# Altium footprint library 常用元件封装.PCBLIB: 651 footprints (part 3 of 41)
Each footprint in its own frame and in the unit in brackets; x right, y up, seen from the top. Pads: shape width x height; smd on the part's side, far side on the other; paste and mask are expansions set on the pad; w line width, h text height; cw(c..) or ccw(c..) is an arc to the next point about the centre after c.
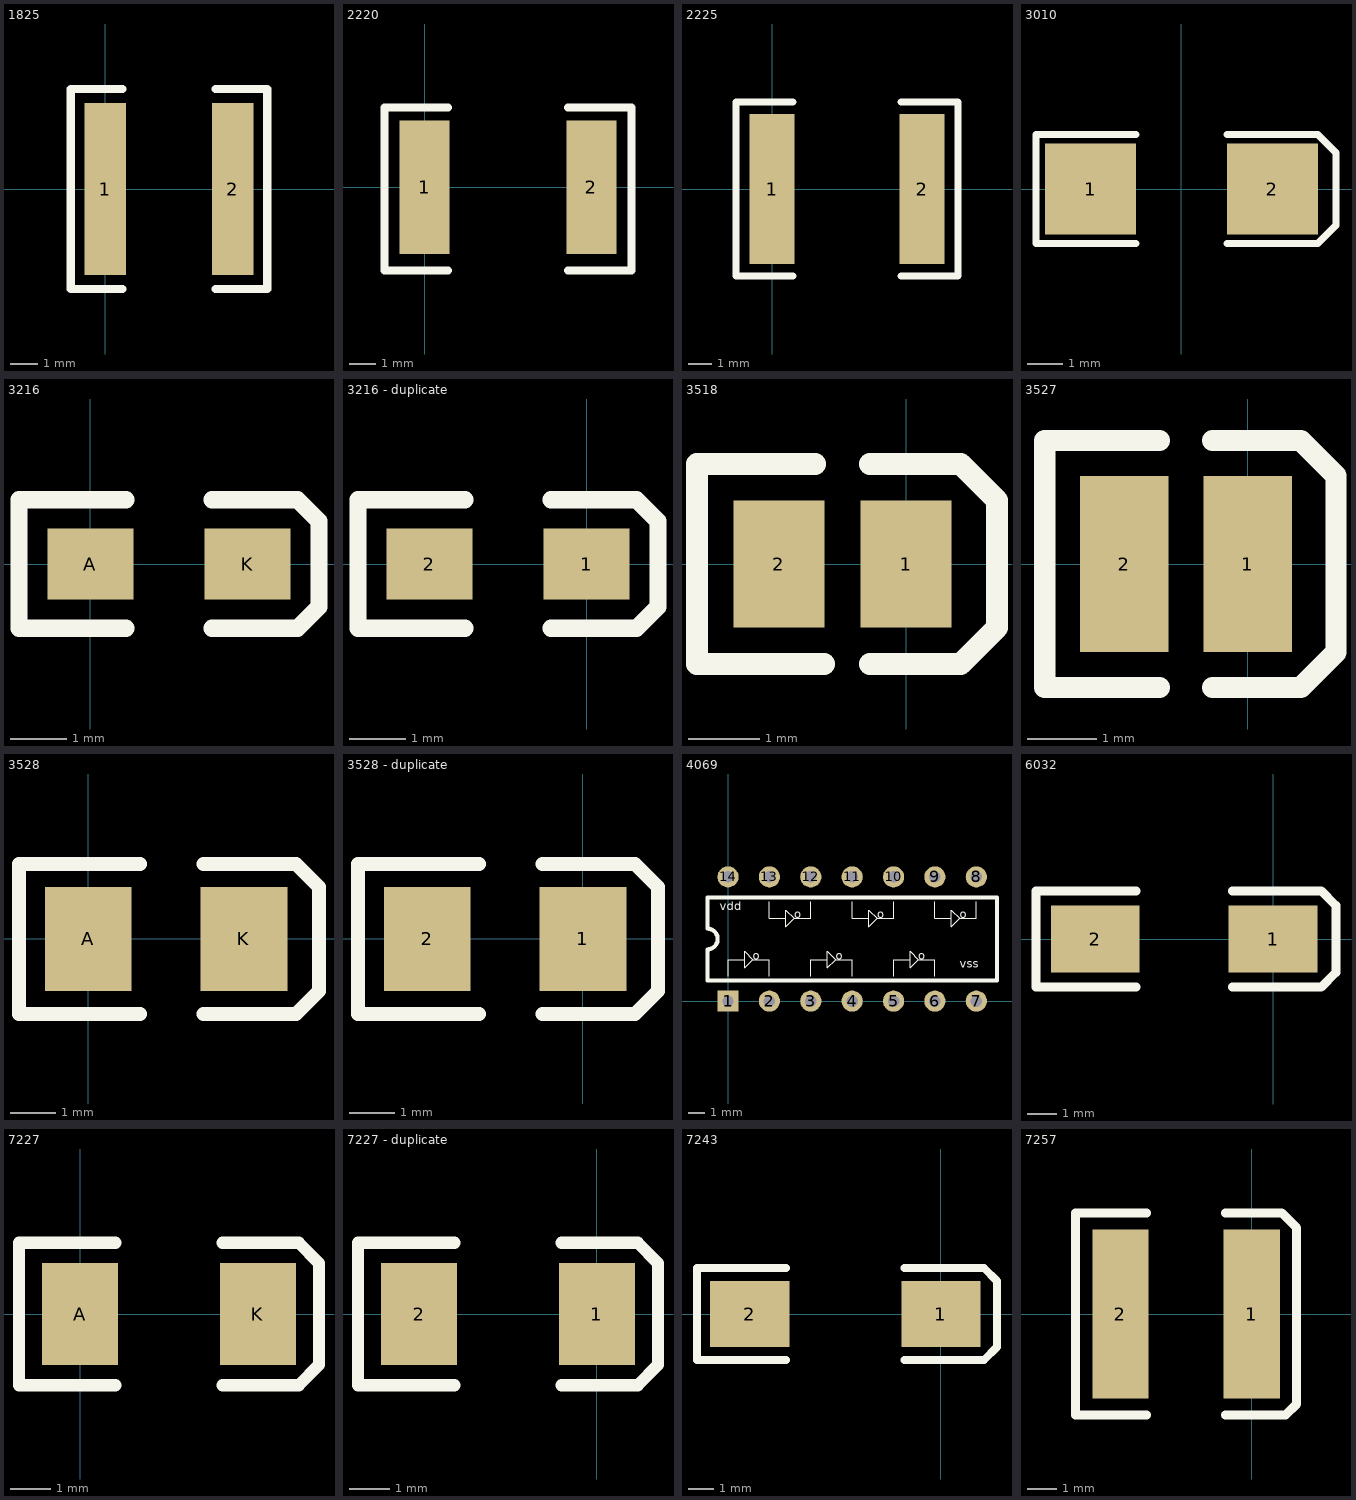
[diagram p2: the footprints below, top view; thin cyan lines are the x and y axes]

## 1825 [mil]
pads (2):
  rect 60x250 smd: 1(0,0) 2(185,0)
TopOverlay:
  lines w12: 25,-145 -50,-145 -50,145 25,145 ; 160,-145 235,-145 235,145 160,145

## 2220 [mil]
pads (2):
  rect 75x200 smd: 1(0,0) 2(250,0)
TopOverlay:
  lines w12: 35,-125 -60,-125 -60,120 35,120 ; 215,-125 310,-125 310,120 215,120

## 2225 [mil]
pads (2):
  rect 75x250 smd: 1(0,0) 2(250,0)
TopOverlay:
  lines w12: 35,-145 -60,-145 -60,145 35,145 ; 215,-145 310,-145 310,145 215,145

## 3010 [mil]
pads (2):
  rect 100x100 smd: 1(-100,0) 2(100,0)
TopOverlay:
  lines w8: -50,-60 -160,-60 -160,-50 -160,60 -50,60 ; 50,60 150,60 170,40 170,-40 150,-60 50,-60 80,-60

## 3216 [mil]
pads (2):
  rect 60x50 smd: A(0,0) K(110,0)
TopOverlay:
  lines w12: 25,-45 -50,-45 -50,45 25,45 ; 85,-45 145,-45 160,-30 160,30 145,45 85,45

## 3216 - duplicate [mil]
pads (2):
  rect 60x50 smd: 1(0,0) 2(-110,0)
TopOverlay:
  lines w12: -85,-45 -160,-45 -160,45 -85,45 ; -25,-45 35,-45 50,-30 50,30 35,45 -25,45

## 3518 [mil]
pads (2):
  rect 50x70 smd: 1(0,0) 2(-70,0)
TopOverlay:
  lines w12: -50,55 -115,55 -115,-55 -45,-55 ; -20,-55 30,-55 50,-35 50,35 30,55 -20,55

## 3527 [mil]
pads (2):
  rect 50x100 smd: 1(0,0) 2(-70,0)
TopOverlay:
  lines w12: -50,-70 -115,-70 -115,70 -50,70 ; -20,-70 30,-70 50,-50 50,50 30,70 -20,70

## 3528 [mil]
pads (2):
  rect 75x90 smd: A(0,0) K(135,0)
TopOverlay:
  lines w12: 45,-65 -60,-65 -60,65 45,65 ; 100,-65 180,-65 200,-45 200,45 180,65 100,65

## 3528 - duplicate [mil]
pads (2):
  rect 75x90 smd: 1(0,0) 2(-135,0)
TopOverlay:
  lines w12: -90,-65 -195,-65 -195,65 -90,65 ; -35,-65 45,-65 65,-45 65,45 45,65 -35,65

## 4069 [mm]
pads (14):
  rect 1.3x1.3 hole 0.7: 1(0,0)
  round 1.3 hole 0.7: 2(2.54,0) 3(5.08,0) 4(7.62,0) 5(10.16,0) 6(12.7,0) 7(15.24,0) 8(15.24,7.62) 9(12.7,7.62) 10(10.16,7.62) 11(7.62,7.62) 12(5.08,7.62) 13(2.54,7.62) 14(0,7.62)
TopOverlay:
  lines w0.051: 0,1.524 0,2.54 0.508,2.54 1.016,2.54 ; 2.54,1.524 2.54,2.54 1.524,2.54 ; 2.54,6.096 2.54,5.08 3.048,5.08 3.556,5.08 ; 5.08,1.524 5.08,2.54 5.588,2.54 6.096,2.54 ; 5.08,6.096 5.08,5.08 4.064,5.08 ; 7.62,1.524 7.62,2.54 6.604,2.54 ; 7.62,6.096 7.62,5.08 8.128,5.08 8.636,5.08 ; 10.16,1.524 10.16,2.54 10.668,2.54 11.176,2.54 ; 10.16,6.096 10.16,5.08 9.144,5.08 ; 12.7,1.524 12.7,2.54 11.684,2.54 ; 12.7,6.096 12.7,5.08 13.208,5.08 13.716,5.08 ; 15.24,6.096 15.24,5.08 14.224,5.08 ; 1.524,2.54 1.016,2.032 1.016,3.048 1.524,2.54 ; 4.064,5.08 3.556,4.572 3.556,5.588 4.064,5.08 ; 6.604,2.54 6.096,2.032 6.096,3.048 6.604,2.54 ; 9.144,5.08 8.636,4.572 8.636,5.588 9.144,5.08 ; 11.684,2.54 11.176,2.032 11.176,3.048 11.684,2.54 ; 14.224,5.08 13.716,4.572 13.716,5.588 14.224,5.08
  lines w0.254: -1.27,1.27 16.51,1.27 16.51,6.35 -1.27,6.35 -1.27,4.445 cw(c-1.27,3.81) -1.27,3.175 -1.27,1.27
  text "vss" at 14.224,2.032 h0.51
  text "vdd" at -0.508,5.588 h0.51
  text "o" at 4.064,5.08 h0.51
  text "o" at 9.144,5.08 h0.51
  text "o" at 14.224,5.08 h0.51
  text "o" at 11.684,2.54 h0.51
  text "o" at 6.604,2.54 h0.51
  text "o" at 1.524,2.54 h0.51

## 6032 [mil]
pads (2):
  rect 120x90 smd: 1(0,0) 2(-240,0)
TopOverlay:
  lines w12: -185,-65 -320,-65 -320,65 -185,65 ; -55,-65 65,-65 85,-45 85,45 65,65 -55,65

## 7227 [mil]
pads (2):
  rect 75x100 smd: A(0,0) K(175,0)
TopOverlay:
  lines w12: 35,-70 -60,-70 -60,70 35,70 ; 140,-70 215,-70 235,-50 235,50 215,70 140,70

## 7227 - duplicate [mil]
pads (2):
  rect 75x100 smd: 1(0,0) 2(-175,0)
TopOverlay:
  lines w12: -140,-70 -235,-70 -235,70 -140,70 ; -35,-70 40,-70 60,-50 60,50 40,70 -35,70

## 7243 [mil]
pads (2):
  rect 120x100 smd: 1(0,0) 2(-290,0)
TopOverlay:
  lines w12: -235,-70 -370,-70 -370,70 -235,70 ; -55,-70 65,-70 85,-50 85,50 65,70 -55,70

## 7257 [mil]
pads (2):
  rect 75x225 smd: 1(0,0) 2(-175,0)
TopOverlay:
  lines w12: -140,-135 -235,-135 -235,135 -140,135 ; -35,-135 45,-135 60,-120 60,115 40,135 -35,135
